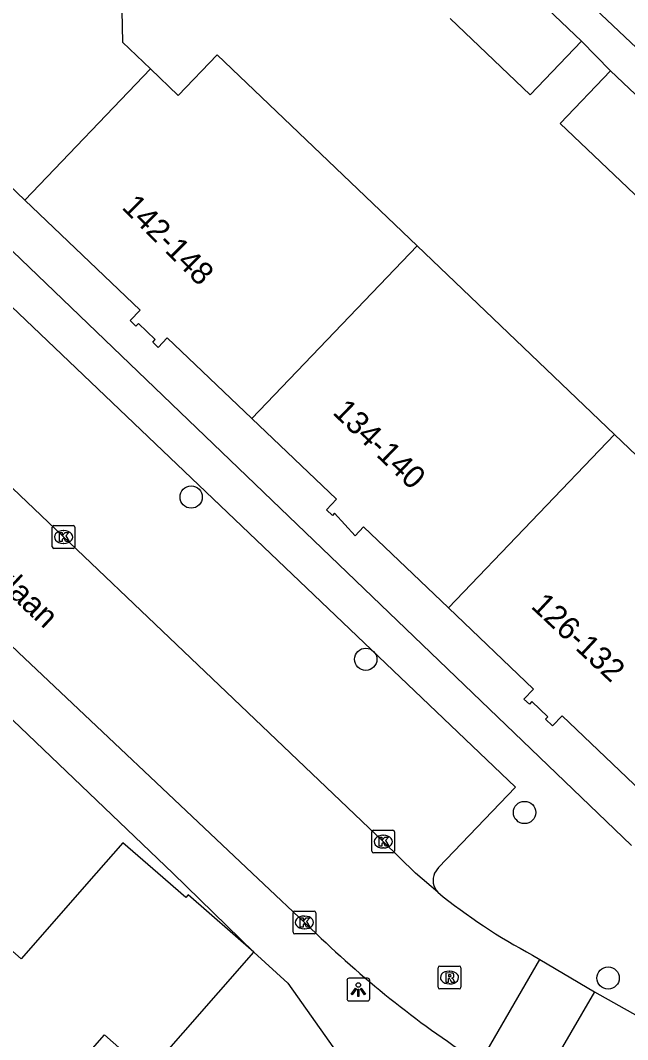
# Model space of a CAD drawing. Extents: x 158474 to 159560, y 388525 to 389605.
# Drawn here: x 159027.05 to 159053.73, y 388742.68 to 388787.5 of the extents above; entities that cross this region are included whole.
import ezdxf

# ---------------------------------------------------------------- set-up
doc = ezdxf.new("R2010")
doc.units = 0
for name, color, linetype in [('IMGEO_Boom', 7, 'Continuous'), ('IMGEO_Kolk', 7, 'Continuous'), ('IMGEO_Lichtpunt', 7, 'Continuous'), ('IMGEO_Openbare_ruimte_label', 7, 'Continuous'), ('IMGEO_Pand', 7, 'Continuous'), ('IMGEO_Pand_nummerreeks', 7, 'Continuous'), ('IMGEO_Rijbaan_lokaal_open', 7, 'Continuous'), ('IMGEO_Rioolput', 7, 'Continuous'), ('IMGEO_Voetpad_open', 7, 'Continuous')]:
    doc.layers.add(name, color=color, linetype=linetype)

msp = doc.modelspace()

# ---------------------------------------------------------------- linework, layer by layer
at = {"layer": 'IMGEO_Boom'}
for centre in [(159034.556, 388766.54), (159042.227, 388759.409), (159049.204, 388752.671), (159052.876, 388745.39)]:
    msp.add_circle(centre, 0.489, dxfattribs=at)
at = {"layer": 'IMGEO_Kolk'}
for p, q in [((159028.524, 388765.285), (159029.376, 388765.285)), ((159028.449, 388764.359), (159028.449, 388765.211)), ((159028.937, 388765.065), (159028.962, 388765.065)), ((159029.45, 388765.211), (159029.45, 388764.359)), ((159028.96, 388764.505), (159028.935, 388764.505)), ((159029.376, 388764.285), (159028.524, 388764.285)), ((159042.57, 388751.89), (159043.422, 388751.89)), ((159042.495, 388750.964), (159042.495, 388751.816)), ((159042.983, 388751.67), (159043.008, 388751.67)), ((159043.496, 388751.816), (159043.496, 388750.964)), ((159043.006, 388751.11), (159042.981, 388751.11)), ((159043.422, 388750.89), (159042.57, 388750.89)), ((159039.03, 388747.407), (159039.03, 388748.259)), ((159039.105, 388748.333), (159039.957, 388748.333)), ((159040.031, 388748.259), (159040.031, 388747.407)), ((159039.518, 388748.113), (159039.543, 388748.113)), ((159039.541, 388747.553), (159039.516, 388747.553)), ((159039.957, 388747.333), (159039.105, 388747.333))]:
    msp.add_line(p, q, dxfattribs=at)
for points in [[(159028.524, 388765.285), (159029.376, 388765.285)], [(159028.449, 388764.359), (159028.449, 388765.211)], [(159028.77, 388764.985), (159028.893, 388764.985), (159028.893, 388764.834), (159029.023, 388764.985), (159029.187, 388764.985), (159029.041, 388764.834), (159029.194, 388764.585), (159029.042, 388764.585), (159028.957, 388764.749), (159028.893, 388764.682), (159028.893, 388764.585), (159028.77, 388764.585), (159028.77, 388764.985)], [(159029.45, 388765.211), (159029.45, 388764.359)], [(159029.376, 388764.285), (159028.524, 388764.285)], [(159042.57, 388751.89), (159043.422, 388751.89)], [(159042.495, 388750.964), (159042.495, 388751.816)], [(159042.816, 388751.59), (159042.939, 388751.59), (159042.939, 388751.439), (159043.069, 388751.59), (159043.233, 388751.59), (159043.087, 388751.439), (159043.24, 388751.19), (159043.088, 388751.19), (159043.003, 388751.354), (159042.939, 388751.287), (159042.939, 388751.19), (159042.816, 388751.19), (159042.816, 388751.59)], [(159043.496, 388751.816), (159043.496, 388750.964)], [(159043.422, 388750.89), (159042.57, 388750.89)], [(159039.03, 388747.407), (159039.03, 388748.259)], [(159039.105, 388748.333), (159039.957, 388748.333)], [(159040.031, 388748.259), (159040.031, 388747.407)], [(159039.351, 388748.033), (159039.474, 388748.033), (159039.474, 388747.882), (159039.604, 388748.033), (159039.768, 388748.033), (159039.622, 388747.882), (159039.775, 388747.633), (159039.623, 388747.633), (159039.538, 388747.797), (159039.474, 388747.73), (159039.474, 388747.633), (159039.351, 388747.633), (159039.351, 388748.033)], [(159039.957, 388747.333), (159039.105, 388747.333)]]:
    msp.add_lwpolyline(points, dxfattribs=at)
for centre, start, end in [((159028.526, 388765.209), 91.552, 178.448), ((159028.526, 388765.209), 91.552, 178.448), ((159029.374, 388765.209), 1.552, 88.448), ((159029.374, 388765.209), 1.552, 88.448), ((159028.526, 388764.361), 181.552, 268.448), ((159028.526, 388764.361), 181.552, 268.448), ((159029.374, 388764.361), 271.552, 358.448), ((159029.374, 388764.361), 271.552, 358.448), ((159042.572, 388751.814), 91.552, 178.448), ((159042.572, 388751.814), 91.552, 178.448), ((159043.42, 388751.814), 1.552, 88.448), ((159043.42, 388751.814), 1.552, 88.448), ((159042.572, 388750.966), 181.552, 268.448), ((159042.572, 388750.966), 181.552, 268.448), ((159043.42, 388750.966), 271.552, 358.448), ((159043.42, 388750.966), 271.552, 358.448), ((159039.107, 388748.257), 91.552, 178.448), ((159039.107, 388748.257), 91.552, 178.448), ((159039.955, 388748.257), 1.552, 88.448), ((159039.955, 388748.257), 1.552, 88.448), ((159039.107, 388747.409), 181.552, 268.448), ((159039.107, 388747.409), 181.552, 268.448), ((159039.955, 388747.409), 271.552, 358.448), ((159039.955, 388747.409), 271.552, 358.448)]:
    msp.add_arc(centre, 0.0765, start, end, dxfattribs=at)
for centre, major_axis, ratio, start_param, end_param in [((159028.936, 388764.785), (-0.387, 0.002), 0.722429, 4.712389, 7.853982), ((159028.961, 388764.785), (-0.39, 0.002), 0.717154, 1.570796, 4.712389), ((159042.982, 388751.39), (-0.387, 0.002), 0.722429, 4.712389, 7.853982), ((159043.007, 388751.39), (-0.39, 0.002), 0.717154, 1.570796, 4.712389), ((159039.517, 388747.833), (-0.387, 0.002), 0.722429, 4.712389, 7.853982), ((159039.542, 388747.833), (-0.39, 0.002), 0.717154, 1.570796, 4.712389)]:
    msp.add_ellipse(centre, major_axis=major_axis, ratio=ratio, start_param=start_param, end_param=end_param, dxfattribs=at)
at = {"layer": 'IMGEO_Lichtpunt'}
for p, q in [((159041.403, 388745.283), (159041.403, 388744.476)), ((159041.403, 388745.283), (159041.403, 388744.476)), ((159042.305, 388745.378), (159041.497, 388745.378)), ((159042.305, 388745.378), (159041.497, 388745.378)), ((159042.399, 388744.476), (159042.399, 388745.283)), ((159042.399, 388744.476), (159042.399, 388745.283)), ((159041.497, 388744.382), (159042.305, 388744.382)), ((159041.497, 388744.382), (159042.305, 388744.382))]:
    msp.add_line(p, q, dxfattribs=at)
for points in [[(159041.777, 388744.947), (159041.816, 388744.919), (159041.628, 388744.657), (159041.59, 388744.684), (159041.777, 388744.947)], [(159041.879, 388744.899), (159041.926, 388744.899), (159041.926, 388744.577), (159041.879, 388744.577), (159041.879, 388744.899)], [(159041.989, 388744.919), (159042.027, 388744.946), (159042.214, 388744.684), (159042.175, 388744.656), (159041.989, 388744.919)]]:
    msp.add_lwpolyline(points, dxfattribs=at)
msp.add_circle((159041.902, 388745.081), 0.0994, dxfattribs=at)
for centre, start, end in [((159041.497, 388745.283), 90, 180), ((159041.497, 388745.283), 90, 180), ((159042.305, 388745.283), 0, 90), ((159042.305, 388745.283), 0, 90), ((159041.497, 388744.476), 180, 270), ((159041.497, 388744.476), 180, 270), ((159042.305, 388744.476), 270, 0), ((159042.305, 388744.476), 270, 360)]:
    msp.add_arc(centre, 0.0946, start, end, dxfattribs=at)
at = {"layer": 'IMGEO_Pand'}
for points in [[(159027.243, 388779.603), (159021.952, 388784.665), (159021.921, 388786.044), (159021.041, 388786.025), (159020.924, 388791.308), (159020.34, 388791.296), (159020.333, 388791.599), (159020.484, 388791.602), (159020.46, 388792.686), (159020.316, 388792.683), (159020.309, 388793.01), (159020.936, 388793.024), (159020.818, 388798.348), (159021.687, 388798.367), (159021.655, 388799.804), (159028.122, 388806.599)], [(159033.926, 388801.027), (159033.753, 388800.845), (159031.284, 388798.25), (159031.543, 388786.548), (159032.767, 388785.377)], [(159048.149, 388789.987), (159051.707, 388786.583)], [(159054.381, 388786.047), (159051.267, 388789.016)], [(159051.707, 388786.583), (159049.45, 388784.225), (159045.935, 388787.589)], [(159032.767, 388785.377), (159033.991, 388784.206), (159035.702, 388785.994), (159044.487, 388777.59)], [(159032.767, 388785.377), (159027.243, 388779.603)], [(159054.321, 388779.578), (159050.767, 388782.962), (159052.985, 388785.29)], [(159052.985, 388785.29), (159056.535, 388781.909)], [(159037.221, 388769.995), (159033.507, 388773.548), (159033.103, 388773.125), (159032.868, 388773.35), (159032.98, 388773.468), (159032.237, 388774.179), (159032.125, 388774.062), (159031.873, 388774.304), (159032.308, 388774.758), (159027.243, 388779.603)], [(159037.221, 388769.995), (159044.487, 388777.59)], [(159044.487, 388777.59), (159053.162, 388769.292)], [(159045.868, 388761.667), (159042.133, 388765.239), (159041.754, 388764.842), (159040.854, 388765.831), (159040.761, 388765.735), (159040.499, 388765.986), (159040.935, 388766.442), (159037.221, 388769.995)], [(159053.162, 388769.292), (159058.316, 388764.362), (159061.929, 388760.905), (159054.647, 388753.293), (159050.851, 388756.925), (159050.425, 388756.479), (159050.121, 388756.77), (159050.227, 388756.881), (159049.529, 388757.549), (159049.414, 388757.429), (159049.179, 388757.653), (159049.602, 388758.095), (159045.868, 388761.667)], [(159053.162, 388769.292), (159045.868, 388761.667)], [(159037.306, 388746.524), (159034.425, 388749.045), (159034.32, 388748.925), (159033.092, 388750), (159031.558, 388751.342), (159030.384, 388750), (159027.089, 388746.235), (159024.448, 388748.546), (159015.603, 388738.438), (159007.562, 388745.475), (159001.992, 388739.111), (159006.048, 388735.562), (159005.044, 388734.415), (159009.336, 388730.659), (159010.325, 388731.789), (159016.379, 388726.491), (159023.453, 388734.575), (159024.568, 388733.599), (159028.355, 388737.927), (159027.25, 388738.894), (159030.744, 388742.887), (159032.658, 388741.213), (159037.306, 388746.524)]]:
    msp.add_lwpolyline(points, dxfattribs=at)
at = {"layer": 'IMGEO_Rijbaan_lokaal_open'}
for points in [[(159045.388, 388749.165), (159044.415, 388750), (159042.993, 388751.391), (159019.504, 388773.791), (159018.088, 388775.372)], [(159023.248, 388763.264), (159026.969, 388759.708), (159037.24, 388750), (159040.067, 388747.327)], [(159047.245, 388741.652), (159049.881, 388746.205)], [(159049.56, 388746.4), (159049.881, 388746.205)], [(159049.881, 388746.205), (159052.273, 388744.789)], [(159052.273, 388744.789), (159049.629, 388740.223)], [(159052.273, 388744.789), (159054.175, 388743.707)]]:
    msp.add_lwpolyline(points, dxfattribs=at)
for centre, radius, start, end in [((159061.346, 388768.714), 25.236, 230.7743, 242.1567), ((159072.299, 388780.718), 46.41, 226.0122, 237.3273)]:
    msp.add_arc(centre, radius, start, end, dxfattribs=at)
at = {"layer": 'IMGEO_Rioolput'}
for p, q in [((159045.405, 388744.986), (159045.405, 388745.838)), ((159045.48, 388745.912), (159046.332, 388745.912)), ((159045.893, 388745.692), (159045.918, 388745.692)), ((159046.406, 388745.838), (159046.406, 388744.986)), ((159045.916, 388745.132), (159045.891, 388745.132)), ((159046.332, 388744.912), (159045.48, 388744.912))]:
    msp.add_line(p, q, dxfattribs=at)
for points in [[(159045.405, 388744.986), (159045.405, 388745.838)], [(159045.48, 388745.912), (159046.332, 388745.912)], [(159045.994, 388745.61), (159045.742, 388745.612), (159045.742, 388745.212)], [(159046.406, 388745.838), (159046.406, 388744.986)], [(159045.742, 388745.212), (159045.866, 388745.212), (159045.866, 388745.374), (159045.877, 388745.374)], [(159045.92, 388745.531), (159045.866, 388745.531), (159045.866, 388745.45)], [(159045.866, 388745.45), (159045.918, 388745.45)], [(159045.924, 388745.345), (159045.995, 388745.212), (159046.135, 388745.212), (159046.07, 388745.338)], [(159046.332, 388744.912), (159045.48, 388744.912)]]:
    msp.add_lwpolyline(points, dxfattribs=at)
for centre, radius, start, end in [((159045.482, 388745.836), 0.0765, 91.552, 178.448), ((159045.482, 388745.836), 0.0765, 91.552, 178.448), ((159045.993, 388745.5), 0.109, 350.3612, 89.416), ((159046.33, 388745.836), 0.0765, 1.552, 88.448), ((159046.33, 388745.836), 0.0765, 1.552, 88.448), ((159045.876, 388745.321), 0.0533, 26.0293, 88.6989), ((159045.902, 388745.639), 0.19, 274.7715, 282.9687), ((159045.926, 388745.435), 0.0964, 77.0061, 93.1865), ((159045.94, 388745.492), 0.0378, 276.6634, 79.6772), ((159045.991, 388745.5), 0.112, 277.5842, 350.9817), ((159045.975, 388745.285), 0.108, 29.5134, 73.7905), ((159045.482, 388744.988), 0.0765, 181.552, 268.448), ((159045.482, 388744.988), 0.0765, 181.552, 268.448), ((159046.33, 388744.988), 0.0765, 271.552, 358.448), ((159046.33, 388744.988), 0.0765, 271.552, 358.448)]:
    msp.add_arc(centre, radius, start, end, dxfattribs=at)
for centre, major_axis, ratio, start_param, end_param in [((159045.892, 388745.412), (-0.387, 0.002), 0.722429, 4.712389, 7.853982), ((159045.917, 388745.412), (-0.39, 0.002), 0.717154, 1.570796, 4.712389)]:
    msp.add_ellipse(centre, major_axis=major_axis, ratio=ratio, start_param=start_param, end_param=end_param, dxfattribs=at)
at = {"layer": 'IMGEO_Voetpad_open'}
for points in [[(159051.707, 388786.583), (159052.985, 388785.29)], [(159053.902, 388751.219), (159017.507, 388786.184)], [(159019.232, 388775.379), (159022.536, 388778.843), (159048.808, 388753.789), (159045.427, 388750.245), (159045.254, 388750)], [(159020.525, 388760.662), (159022.695, 388760.564), (159033.754, 388750), (159037.306, 388746.524)], [(159037.306, 388746.524), (159038.809, 388745.171), (159041.036, 388742.015), (159041.709, 388741.062), (159043.209, 388738.936)]]:
    msp.add_lwpolyline(points, dxfattribs=at)
msp.add_arc((159045.955, 388749.684), 0.769, 155.7641, 222.4699, dxfattribs=at)

# ---------------------------------------------------------------- texts
at = {"layer": 'IMGEO_Openbare_ruimte_label'}
msp.add_text('Chamonixlaan', height=1, rotation=316.5394, dxfattribs=at).set_placement((159021.921, 388766.596))
at = {"layer": 'IMGEO_Pand_nummerreeks'}
for s, rotation, p in [('142-148', 315, (159031.465, 388779.247)), ('134-140', 315.9444, (159040.727, 388770.229)), ('126-132', 316.8705, (159049.443, 388761.697))]:
    msp.add_text(s, height=1, rotation=rotation, dxfattribs=at).set_placement(p)

doc.saveas('drawing.dxf')
